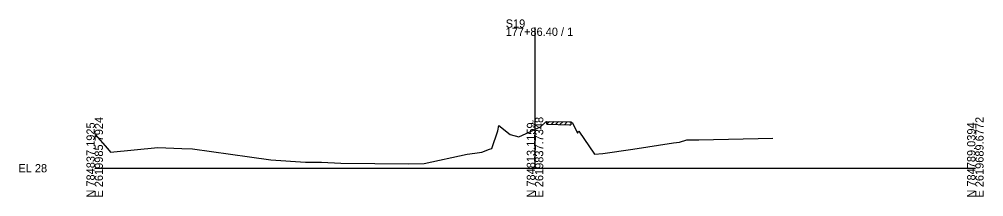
# Model space of a CAD drawing. Extents: x -26 to 1603, y -10 to 5028.
# Drawn here: x 1274.3 to 1602.8, y 990.3 to 1050.7 of the extents above; entities that cross this region are included whole.
import ezdxf

# ---------------------------------------------------------------- set-up
doc = ezdxf.new("R2010")
doc.units = 0
for name, color, linetype in [('RD_GPK_XS_Cell', 7, 'Continuous'), ('RD_XS_ExGround', 7, 'Continuous'), ('RD_XS_ExPaveRet', 7, 'Continuous'), ('RD_XS_TX_Elev_EX', 7, 'Continuous')]:
    doc.layers.add(name, color=color, linetype=linetype)

msp = doc.modelspace()

# ---------------------------------------------------------------- linework, layer by layer
at = {"layer": 'RD_GPK_XS_Cell'}
for p, q in [((1450, 1000), (1450, 1047.86)), ((1300, 1000), (1450, 1000)), ((1450, 1000), (1600, 1000))]:
    msp.add_line(p, q, dxfattribs=at)
at = {"layer": 'RD_XS_ExGround'}
for p, q in [((1451.82, 1014.14), (1453.68, 1015.81)), ((1453.68, 1015.81), (1453.99, 1015.95)), ((1453.99, 1015.95), (1461.7, 1015.78)), ((1461.7, 1015.78), (1462.16, 1015.76)), ((1462.16, 1015.76), (1462.75, 1015.41)), ((1462.75, 1015.41), (1464.42, 1011.89)), ((1435.25, 1006.68), (1437.32, 1012.72)), ((1437.32, 1012.72), (1437.7, 1014.6)), ((1437.7, 1014.6), (1441.57, 1011.52)), ((1444.47, 1010.66), (1449.66, 1013.09)), ((1449.66, 1013.09), (1450, 1013.26)), ((1450, 1013.26), (1451.82, 1014.14)), ((1464.42, 1011.89), (1464.93, 1012.59)), ((1464.93, 1012.59), (1470.23, 1004.75)), ((1300, 1011.49), (1300.17, 1011.49)), ((1300.17, 1011.49), (1304.37, 1006.75)), ((1441.57, 1011.52), (1444.47, 1010.66)), ((1483.33, 1006.48), (1497.15, 1008.67)), ((1497.15, 1008.67), (1499.24, 1008.83)), ((1499.24, 1008.83), (1501.69, 1009.7)), ((1501.69, 1009.7), (1505.82, 1009.72)), ((1505.82, 1009.72), (1531.04, 1010.24)), ((1304.37, 1006.75), (1305.38, 1005.52)), ((1305.38, 1005.52), (1321.48, 1007.01)), ((1321.48, 1007.01), (1329.63, 1006.73)), ((1329.63, 1006.73), (1333.32, 1006.6)), ((1333.32, 1006.6), (1352.73, 1003.85)), ((1429.52, 1005.17), (1431.9, 1005.46)), ((1431.9, 1005.46), (1434.54, 1006.54)), ((1434.54, 1006.54), (1435.25, 1006.68)), ((1473.12, 1005.06), (1483.33, 1006.48)), ((1352.73, 1003.85), (1359.97, 1002.87)), ((1359.97, 1002.87), (1371.77, 1002.03)), ((1371.77, 1002.03), (1377.29, 1002.1)), ((1377.29, 1002.1), (1383.83, 1001.74)), ((1412.24, 1001.57), (1426.83, 1004.77)), ((1426.83, 1004.77), (1429.52, 1005.17)), ((1470.23, 1004.75), (1473.12, 1005.06)), ((1383.83, 1001.74), (1407.03, 1001.47)), ((1407.03, 1001.47), (1412.24, 1001.57))]:
    msp.add_line(p, q, dxfattribs=at)
at = {"layer": 'RD_XS_ExPaveRet'}
for p, q in [((1453.99, 1014.95), (1453.99, 1015.95)), ((1453.99, 1014.95), (1454.97, 1015.93)), ((1455.49, 1014.92), (1456.47, 1015.9)), ((1456.99, 1014.89), (1457.97, 1015.87)), ((1458.49, 1014.85), (1459.47, 1015.83)), ((1459.99, 1014.82), (1460.97, 1015.8)), ((1462.16, 1015.76), (1462.16, 1014.76)), ((1453.99, 1014.95), (1461.7, 1014.78)), ((1461.7, 1014.78), (1462.16, 1014.76))]:
    msp.add_line(p, q, dxfattribs=at)

# ---------------------------------------------------------------- texts
at = {"layer": 'RD_GPK_XS_Cell'}
for s, p in [('S19', (1440, 1047.86)), ('177+86.40 / 1', (1440, 1045.06)), ('EL 28', (1274, 998.6))]:
    msp.add_text(s, height=2.8, dxfattribs=at).set_placement(p)
for s, p in [('N 784837.1925', (1300, 990)), ('E 2619985.7924', (1302.8, 990)), ('N 784813.1159', (1450, 990)), ('E 2619837.7348', (1452.8, 990)), ('N 784789.0394', (1600, 990)), ('E 2619689.6772', (1602.8, 990))]:
    msp.add_text(s, height=2.8, rotation=90, dxfattribs=at).set_placement(p)
at = {"layer": 'RD_XS_TX_Elev_EX'}
msp.add_text('41.26', height=0.8, rotation=90, dxfattribs=at).set_placement((1449.9, 1013.76))

doc.saveas('drawing.dxf')
